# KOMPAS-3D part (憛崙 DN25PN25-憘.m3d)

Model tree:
1. Объединить компоненты:1  (labels: СЕНС DN25PN25)
2. Эскиз:1
3. Операция выдавливания:1
     Расстояние 1 = 14
4. Фаска:1
     Угол = 45; Длина 1 = 2; Длина 2 = 2

Referenced files in D:\Савин\!СЕНСОР\3D для заказчика\!Новый перечень\СЕНС\1. СЕНС\DN25\: СЕНС DN25PN25.a3d
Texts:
  СЕНС DN25PN25-СВ
  ООО НПП Сенсор
  СЕНС DN25PN25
